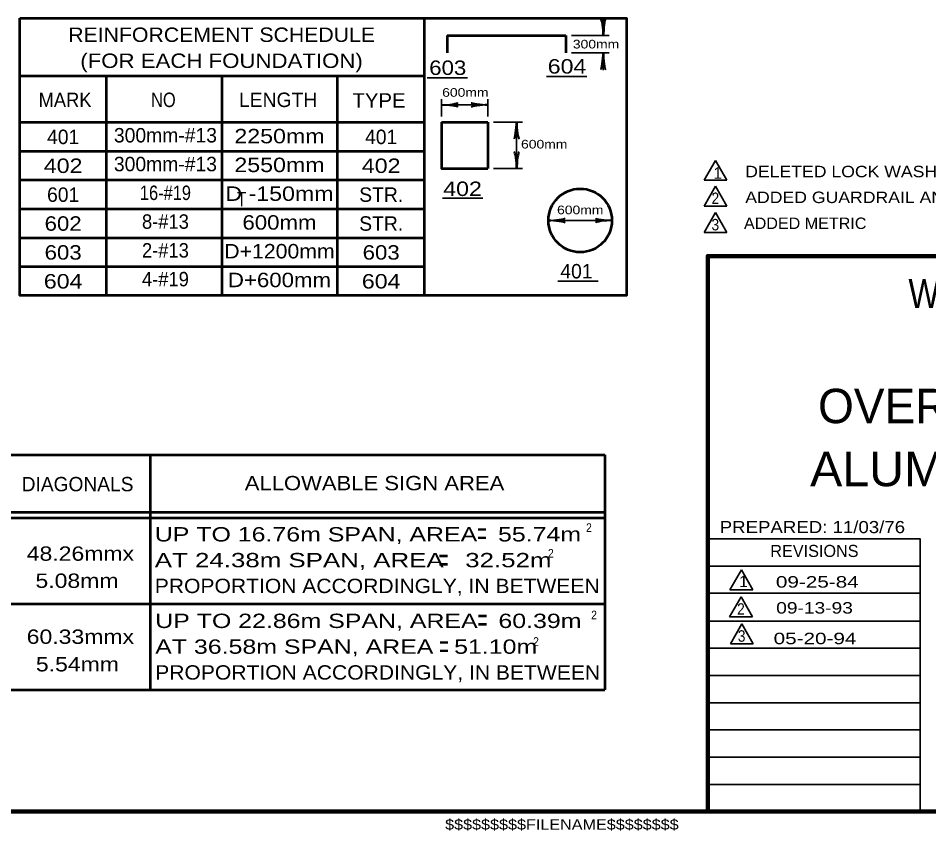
# Model space of a CAD drawing. Extents: x -29 to 827, y -14 to 530.
# Drawn here: x 457.6 to 648.3, y -6.9 to 163.3 of the extents above; entities that cross this region are included whole.
import ezdxf
from ezdxf.enums import TextEntityAlignment as Align

# ---------------------------------------------------------------- set-up
doc = ezdxf.new("R2010")
doc.units = 0
doc.header["$LTSCALE"] = 0.97
doc.layers.add('1', color=7, linetype='Continuous', lineweight=53)

msp = doc.modelspace()

# ---------------------------------------------------------------- linework, layer by layer
at = {"layer": '1'}
for p, q in [((542.6759, 163.2574), (542.6759, 105.2014)), ((547.4999, 159.6334), (572.2919, 159.6334)), ((547.4999, 159.6334), (547.4999, 155.9854)), ((572.2919, 159.6334), (572.2919, 155.9854)), ((458.0039, 151.1614), (542.6759, 151.1614)), ((476.1479, 105.2014), (476.1479, 151.1614)), ((500.3399, 105.2014), (500.3399, 151.1614)), ((524.5319, 105.2014), (524.5319, 151.1614)), ((458.0039, 141.4894), (542.6759, 141.4894)), ((546.2999, 141.4894), (555.9719, 141.4894)), ((555.9719, 141.4894), (555.9719, 131.7934)), ((458.0039, 135.4414), (542.6759, 135.4414)), ((458.0039, 129.3934), (542.6759, 129.3934)), ((458.0039, 123.3454), (542.6759, 123.3454)), ((458.0039, 117.2974), (542.6759, 117.2974)), ((458.0039, 111.2494), (542.6759, 111.2494)), ((485.2642, 71.8697), (485.2642, 22.6697)), ((580.4623, 71.8697), (580.4623, 22.6697)), ((221.2642, 59.8697), (580.4623, 59.8697)), ((221.2642, 58.6697), (580.4623, 58.6697)), ((221.2642, 40.6697), (580.4623, 40.6697)), ((221.2642, 22.6697), (580.4623, 22.6697))]:
    msp.add_line(p, q, dxfattribs=at)
at = {"layer": '1', "lineweight": 35}
for p, q in [((580.1639, 159.6334), (580.1639, 163.2574)), ((573.5159, 159.6334), (581.3639, 159.6334)), ((573.5159, 155.9854), (581.3639, 155.9854)), ((580.1639, 155.9854), (580.1639, 152.3614)), ((543.2759, 150.8014), (551.7479, 150.8014)), ((568.2599, 151.0894), (576.7079, 151.0894)), ((546.2999, 142.6894), (546.2999, 146.3134)), ((546.2999, 145.1134), (555.9719, 145.1134)), ((555.9719, 142.6894), (555.9719, 146.3134)), ((557.1719, 141.4894), (563.2199, 141.4894)), ((562.0199, 141.4894), (562.0199, 131.7934)), ((603.6543, 133.4905), (601.2543, 129.3336)), ((603.6543, 133.4905), (606.0543, 129.3336)), ((557.1719, 131.7934), (563.2199, 131.7934)), ((606.0543, 129.3336), (601.2543, 129.3336)), ((603.6643, 128.0864), (601.2643, 123.9295)), ((603.6643, 128.0864), (606.0643, 123.9295)), ((546.4919, 125.5534), (554.9639, 125.5534)), ((606.0643, 123.9295), (601.2643, 123.9295)), ((603.6643, 122.5721), (601.2643, 118.4152)), ((603.6643, 122.5721), (606.0643, 118.4152)), ((581.9879, 120.9214), (568.6679, 120.9214)), ((606.0643, 118.4152), (601.2643, 118.4152)), ((570.6119, 108.2014), (579.0599, 108.2014)), ((646.5407, 48.5545), (602.0407, 48.5545)), ((609.0939, 47.7569), (606.6939, 43.6)), ((609.0939, 47.7569), (611.4939, 43.6)), ((646.5407, 42.8545), (602.0407, 42.8545)), ((609.0229, 42.1044), (606.6229, 37.9475)), ((611.4939, 43.6), (606.6939, 43.6)), ((609.0229, 42.1044), (611.4229, 37.9475)), ((646.5407, 37.0545), (602.0407, 37.0545)), ((611.4229, 37.9475), (606.6229, 37.9475)), ((609.1727, 36.455), (606.7727, 32.2981)), ((609.1727, 36.455), (611.5727, 32.2981)), ((646.5407, 31.3545), (602.0407, 31.3545)), ((611.5727, 32.2981), (606.7727, 32.2981)), ((646.5407, 25.6545), (602.0407, 25.6545)), ((646.5407, 19.9545), (602.0407, 19.9545)), ((646.5407, 14.2545), (602.0407, 14.2545)), ((646.5407, 8.5545), (602.0407, 8.5545)), ((646.5407, 2.8545), (602.0407, 2.8545))]:
    msp.add_line(p, q, dxfattribs=at)
at = {"layer": '1', "lineweight": 158}
msp.add_line((820.0407, -2.8455), (28.4407, -2.8455), dxfattribs=at)
at = {"layer": '1'}
msp.add_lwpolyline([(458.0039, 163.2574), (585.0119, 163.2574), (585.0119, 105.2014), (458.0039, 105.2014)], close=True, dxfattribs=at)
for points in [[(546.2999, 141.4894), (546.2999, 131.7934), (555.9719, 131.7934)], [(221.2642, 71.8697), (329.2642, 71.8697), (425.2642, 71.8697), (580.4623, 71.8697)]]:
    msp.add_lwpolyline(points, dxfattribs=at)
at = {"layer": '1', "lineweight": 158}
msp.add_lwpolyline([(602.0407, -2.8455), (602.0407, 113.4545), (820.0407, 113.4545)], dxfattribs=at)
at = {"layer": '1', "lineweight": 35}
msp.add_lwpolyline([(646.5407, -2.8455), (646.5407, 54.2545), (602.0407, 54.2545)], dxfattribs=at)
at = {"layer": '1'}
msp.add_circle((575.3252, 120.915), 6.6528, dxfattribs=at)
at = {"layer": '1', "lineweight": 40}
for centre, major_axis, ratio, start_param, end_param in [((579.8294, 160.9422), (0.1889, -2.16), 0.122415, 0.89635335, 3.14159265), ((579.8294, 160.9422), (0.1889, -2.16), 0.122415, 0.89635335, 3.14159265), ((580.4196, 160.9776), (-0.2125, -2.1246), 0.07063, 3.14071475, 5.41810995), ((580.4196, 160.9776), (-0.2125, -2.1246), 0.07063, 3.14071475, 5.41810995), ((579.9077, 154.6381), (0.2125, 2.1246), 0.07063, 3.14071475, 5.41810995), ((580.4978, 154.6735), (-0.1889, 2.16), 0.122415, 0.89635335, 3.14159265), ((547.6502, 144.8511), (-2.1246, 0.2125), 0.07063, 3.14071475, 5.41810995), ((547.6147, 145.4413), (-2.16, -0.1889), 0.122415, 0.89635335, 3.14159265), ((554.6517, 144.7728), (2.16, 0.1889), 0.122415, 0.89635335, 3.14159265), ((554.6517, 144.7728), (2.16, 0.1889), 0.122415, 0.89635335, 3.14159265), ((554.6163, 145.363), (2.1246, -0.2125), 0.07063, 3.14071475, 5.41810995), ((554.6163, 145.363), (2.1246, -0.2125), 0.07063, 3.14071475, 5.41810995), ((561.7637, 140.1229), (0.2125, 2.1246), 0.07063, 3.14071475, 5.41810995), ((562.3538, 140.1583), (-0.1889, 2.16), 0.122415, 0.89635335, 3.14159265), ((561.6854, 133.1214), (0.1889, -2.16), 0.122415, 0.89635335, 3.14159265), ((561.6854, 133.1214), (0.1889, -2.16), 0.122415, 0.89635335, 3.14159265), ((562.2756, 133.1568), (-0.2125, -2.1246), 0.07063, 3.14071475, 5.41810995), ((562.2756, 133.1568), (-0.2125, -2.1246), 0.07063, 3.14071475, 5.41810995), ((570.0278, 120.6591), (-2.1246, 0.2125), 0.07063, 3.14071475, 5.41810995), ((569.9923, 121.2493), (-2.16, -0.1889), 0.122415, 0.89635335, 3.14159265), ((580.6581, 120.5808), (2.16, 0.1889), 0.122415, 0.89635335, 3.14159265), ((580.6227, 121.171), (2.1246, -0.2125), 0.07063, 3.14071475, 5.41810995)]:
    msp.add_ellipse(centre, major_axis=major_axis, ratio=ratio, start_param=start_param, end_param=end_param, dxfattribs=at)

# ---------------------------------------------------------------- texts
at = {"layer": '1'}
for s, height, width, p in [('REINFORCEMENT SCHEDULE', 3.024, 1.1, (500.235, 158.2894)), ('(FOR EACH FOUNDATION)', 3.024, 1.15, (500.2178, 152.8414)), ('2250mm', 3.024, 1.2, (512.3456, 137.0649)), ('402', 3.024, 1.2, (467.0436, 130.8574)), ('2550mm', 3.024, 1.2, (512.3456, 131.0409)), ('402', 3.024, 1.2, (533.6436, 130.8574)), ('16-#19', 3.024, 0.85, (488.4643, 125.1944)), ('D -150mm', 3.024, 1.2, (512.3456, 125.0169)), ('8-#13', 3.024, 0.95, (488.4643, 119.1704)), ('600mm', 3.024, 1.15, (512.3456, 118.9929)), ('602', 3.024, 1.15, (467.0447, 118.7614)), ('603', 3.024, 1.15, (467.0447, 112.7134)), ('2-#13', 3.024, 0.95, (488.4643, 113.1464)), ('D+1200mm', 3.024, 1.1, (512.3456, 112.9689)), ('603', 3.024, 1.15, (533.6447, 112.7134)), ('604', 3.024, 1.2, (467.0442, 106.6654)), ('4-#19', 3.024, 0.95, (488.4643, 107.1224)), ('D+600mm', 3.024, 1.15, (512.3456, 106.9449)), ('604', 3.024, 1.2, (533.6442, 106.6654)), ('WEST VIRGINIA DIVISION OF HIGHWAYS', 6.089, 0.85, (711.9407, 102.5545)), ('ALUMINUM COMBINATION (TRUSS)', 7.2, 1.05, (709.4043, 65.2732)), ('48.26mmx', 3, 1.2, (470.6531, 49.6677)), ('5.08mm', 3, 1.2, (469.9429, 43.9877)), ('09-25-84', 2.4, 1.35, (624.9776, 44.0435)), ('09-13-93', 2.4, 1.25, (624.3994, 38.6061)), ('60.33mmx', 3, 1.2, (470.6532, 32.2693)), ('05-20-94', 2.4, 1.35, (624.5031, 32.1949)), ('5.54mm', 3, 1.2, (470.0318, 26.5005))]:
    msp.add_text(s, height=height, dxfattribs=dict(at, width=width)).set_placement(p, align=Align.CENTER)
for s, height, width, p in [('300mm', 1.814, 1.2, (573.7883, 156.9214)), ('604', 3.024, 1.2, (568.5239, 151.6654)), ('603', 3.024, 1.15, (543.7079, 151.3774)), ('MARK', 3.024, 0.95, (461.8919, 144.6574)), ('NO', 3.024, 0.85, (485.4599, 144.6574)), ('TYPE', 3.024, 1.05, (527.6519, 144.5374)), ('600mm', 1.814, 1.2, (546.4226, 146.8078)), ('600mm', 1.814, 1.2, (562.9353, 135.9742)), ('DELETED LOCK WASHERS & ADDED GROUNDING NOTE', 2.4, 1.15, (609.8827, 129.9598)), ('402', 3.024, 1.2, (546.6359, 126.0334)), ('T', 3.024, 0.8, (503.4519, 123.871)), ('2', 2.4, 0.9, (602.8231, 124.3498)), ('ADDED GUARDRAIL AND CURB CLEAR.', 2.4, 1.15, (609.8927, 124.5557)), ('600mm', 1.814, 1.2, (570.4814, 122.2103)), ('3', 2.4, 0.9, (602.8231, 118.8355)), ('ADDED METRIC', 2.4, 1.05, (609.6197, 119.1247)), ('ALLOWABLE SIGN AREA', 3, 1.15, (505.0803, 64.4231)), ('2', 1.8, 0.9, (576.5541, 55.7094)), ('PREPARED: 11/03/76', 2.537, 1.15, (604.5407, 55.4545)), ('UP TO 16.76m SPAN, AREA   55.74m', 3, 1.3, (486.2348, 53.702)), ('=', 4.8, 0.55, (553.74, 53.0508)), ('2', 1.8, 0.9, (568.5811, 50.3344)), ('AT 24.38m SPAN, AREA   32.52m', 3, 1.35, (486.2348, 48.302)), ('=', 4.8, 0.55, (545.6806, 47.4983)), ('PROPORTION ACCORDINGLY, IN BETWEEN', 3, 1.1, (486.2348, 42.902)), ('2', 2.4, 0.9, (608.1817, 38.3678)), ('UP TO 22.86m SPAN, AREA   60.39m', 3, 1.3, (486.3236, 35.5869)), ('=', 4.8, 0.55, (553.8288, 34.9357)), ('2', 1.8, 0.9, (577.6194, 37.4167)), ('3', 2.4, 0.9, (608.3315, 32.7184)), ('AT 36.58m SPAN, AREA   51.10m', 3, 1.3, (486.3236, 30.1869)), ('=', 4.8, 0.55, (545.7694, 29.3832)), ('2', 1.8, 0.9, (565.4739, 31.8641)), ('PROPORTION ACCORDINGLY, IN BETWEEN', 3, 1.1, (486.3236, 24.7869)), ('$$$$$$$$$FILENAME$$$$$$$$', 2.2, 1.15, (547.0407, -6.6455))]:
    msp.add_text(s, height=height, dxfattribs=dict(at, width=width)).set_placement(p)
for s, height, p in [('LENGTH', 3.024, (503.8679, 144.6574)), ('1', 2.4, (603.2384, 129.6475)), ('401', 3.024, (571.1639, 108.7774)), ('DIAGONALS', 3, (458.3622, 64.2148)), ('REVISIONS', 2.537, (615.1407, 50.4545)), ('1', 2.4, (608.6462, 44.1536))]:
    msp.add_text(s, height=height, dxfattribs=at).set_placement(p)
for s, height, p in [('401', 3.024, (467.0487, 136.9054)), ('300mm-#13', 3.024, (488.4643, 137.2424)), ('401', 3.024, (533.6486, 136.9054)), ('300mm-#13', 3.024, (488.4643, 131.2184)), ('601', 3.024, (467.0498, 124.8094)), ('STR.', 3.024, (533.6506, 124.8094)), ('STR.', 3.024, (533.6506, 118.7614)), ('OVERHEAD SIGN SUPPORT, STEEL-', 7.2, (709.4042, 78.4732))]:
    msp.add_text(s, height=height, dxfattribs=at).set_placement(p, align=Align.CENTER)

doc.saveas('drawing.dxf')
